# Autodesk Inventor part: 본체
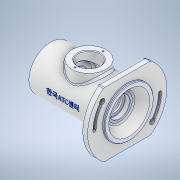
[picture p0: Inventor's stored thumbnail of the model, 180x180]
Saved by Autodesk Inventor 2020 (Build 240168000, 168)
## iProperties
Created: 2022-05
Part Number: 본체
Material: 알루미늄 6061
Document SubType Name: Modeling
Designer: Student
Mass: 685.464 g
Surface Area: 627.299 cm^2
Volume: 253.876 cm^3
Density: 2.7 g/cm^3
Appearance: 알루미늄 - 평지
Author: Student
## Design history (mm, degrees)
sketch "스케치1"
  geometry: L1 (-97.293, 0)-(97.293, 0); L2 (-51, 0)-(-51, 32); L3 (-51, 32)-(51, 32); L4 (51, 32)-(51, 58); L5 (51, 58)-(61, 58); L6 (61, 58)-(61, 36); L7 (61, 36)-(64, 36); L8 (64, 36)-(64, 0); 4 further points
  constraints: 16 end point, 4 perpendicular, 3 coincident, 3 midpoint, 2 horizontal, 2 point on line, 1 parallel, 1 vertical, 1 vertical alignment
  dimensions: "d5" = 64 diameter of L3 L1; "d6" = 116 diameter of L5 L1; "d7" = 72 diameter of L7 L1; "d8" = 102 distance between parallel lines of L4 L2; "d9" = 13 distance between parallel lines of L8 L4; "d10" = 3 distance of L6.end L7.end
revolve "회전1" sketch "스케치1" stored, may be unused: angle "d11" = 90 deg
sketch "스케치2"
  geometry: L1 (-76.744, 0)-(76.744, 0); L2 (-51, 22.5)-(-43, 22.5); L3 (-43, 22.5)-(-43, 24); L4 (-43, 24)-(-40, 24); L5 (-40, 24)-(-40, 22.5); L6 (-40, 22.5)-(-29, 22.5); L7 (-29, 22.5)-(-29, 17.5); L8 (-29, 17.5)-(-26.75, 17.5); L9 (-26.75, 17.5)-(-26.75, 18.5); L10 (-26.75, 18.5)-(-25, 18.5); L11 (-25, 18.5)-(-25, 17.5); L12 (-25, 17.5)-(-14, 17.5); L13 (-14, 17.5)-(-14, 27); L14 (-14, 27)-(24, 27); L15 (24, 27)-(24, 17.5); L16 (24, 17.5)-(35, 17.5); L17 (35, 17.5)-(35, 15); L18 (35, 15)-(40, 15); L19 (40, 15)-(40, 11); L20 (40, 11)-(42.7, 11); L21 (42.7, 11)-(42.7, 15); L22 (42.7, 15)-(49.3, 15); L23 (64, -36)-(64, 36) reference; L24 (64, 30)-(64, 0); L25 (-51, -32)-(-51, 32) reference; L26 (-51, 22.5)-(-51, 0); L27 (50, 15.404)-(50, 20); L28 (50, 20)-(64, 30); L29 (49.3, 15)-(50, 15.404); 5 further points
  constraints: 54 end point, 17 perpendicular, 10 point on line, 2 coincident, 2 horizontal, 2 midpoint, 1 parallel, 1 vertical
  dimensions: "d12" = 45 diameter of L2 L1; "d13" = 48 diameter of L4 L1; "d14" = 54 diameter of L14 L1; "d15" = 30 diameter of L18 L1; "d17" = 60 diameter of L24.start L1; "d18" = 40 diameter of L27.end L1; "d19" = 30 diameter of L22 L1; "d20" = 22 diameter of L20 L1; "d21" = 37 diameter of L10 L1; "d22" = 35 diameter of L12 L1; "d23" = 8 distance of L2.start L2.end; "d24" = 3 distance of L3.end L4.end; "d25" = 11 distance of L11.end L12.end; "d26" = 11 distance of L15.end L16.end; "d27" = 14 distance from line of L23 L27.end; "d28" = 5 distance of L17.end L18.end; "d29" = 29 distance between parallel lines of L23 L17; "d30" = 22 distance between parallel lines of L7 L26; "d32" = 1.75 distance of L9.end L10.end; "d33" = 4 distance between parallel lines of L7 L11; "d35" = 150 deg angle of L22 L29; "d36" = 0.7 horizontal distance of L27.start L22.end; "d37" = 7.3 distance between parallel lines of L27 L21
revolve "회전2" sketch "스케치2" stored, may be unused: angle "d34" = 90 deg
node "작업 평면1"
sketch "스케치3"
  geometry: L1 (51, 32)-(51, -32) reference; C1 r 25 at (-5, 0); 1 further point
  constraints: 1 centre point, 1 horizontal alignment
  dimensions: "d39" = 25 radius of C1; "d40" = 56 distance from line of L1 C1.centre
extrude "돌출1" join sketch "스케치3" stored distance "d41" = 10; taper "d42" = 0 deg
sketch "스케치4"
  geometry: C1 r 25 at (0, 0) reference; 1 further point
hole "구멍1" sketch "스케치4" at (0, 0) diameter "d43" = 32; stored, may be unused: countersink angle "d47" = 90 deg, drill point angle "d49" = 0 deg; dims "d44" = 6, "d45" = 4, "d46" = 2, "d48" = 20
sketch "스케치7"
  geometry: L1 (-33.985, 47)-(33.985, 47); L2 (-33.985, -47)-(33.985, -47); A1 r 58 centre (0, 0) between (-33.985, 47) and (-33.985, -47) reference; A2 r 58 centre (0, 0) between (-33.985, -47) and (33.985, -47); A3 r 58 centre (0, 0) between (33.985, 47) and (-33.985, 47); 1 further point
  constraints: 8 point on circle, 4 end point, 2 centre point, 1 coincident, 1 horizontal, 1 parallel
  dimensions: "d68" = 47 distance from line of point (0, 0) L1; "d69" = 47 distance from line of point (0, 0) L2
extrude "돌출4" cut sketch "스케치7" extent not by distance; stored distance "d70" = 0; taper "d71" = 0 deg
sketch "스케치8"
  geometry: C1 r 25 at (0, 0) reference; 2 further points
  constraints: 1 vertical alignment
  dimensions: "d72" = 20.5 distance of C1.centre point (0, 20.5)
hole "구멍2" sketch "스케치8" at (0, 20.5) diameter "d73" = 2.459; stored, may be unused: countersink angle "d77" = 90 deg, drill point angle "d79" = 118 deg; dims "d74" = 6, "d75" = 4, "d76" = 2, "d78" = 8
node "작업 평면2"
sketch "스케치9"
  geometry: L1 (61, -47)-(61, 47) reference; 2 further points
  constraints: 1 horizontal alignment, 1 other
  dimensions: "d84" = 62 distance from line of L1 point (-1, 0)
feature "엠보싱1" sketch "스케치9" dims "d85" = 0.5, "d86" = 0
fillet "모깎기1" dims "d87" = 0.5
fillet "모깎기2" dims "d88" = 0.6
feature "스레드1" dims "d89" = 18, "d90" = 0
fillet "모깎기3" dims "d91" = 3
chamfer "모따기1" distance "d92" = 1; stored, may be unused: second distance "d93" = 2, angle "d94" = 45 deg
sketch "스케치11"
  geometry: L1 (0, 0)-(-47.496, 0); L2 (0, 0)-(42.689, 0); L3 (-36.77, -30.854)-(0, 0); L4 (0, 0)-(36.77, 30.854); A1 r 48 centre (0, 0) between (-48, 0) and (-36.77, -30.854); A2 r 50.25 centre (0, 0) between (-50.25, 0) and (-38.494, -32.3); A3 r 45.75 centre (0, 0) between (-45.75, 0) and (-35.047, -29.408); A4 r 2.25 centre (-48, 0) between (-45.75, 0) and (-50.25, 0); A5 r 2.25 centre (-36.77, -30.854) between (-38.494, -32.3) and (-35.047, -29.408); A6 r 48 centre (0, 0) between (48, 0) and (36.77, 30.854); A7 r 50.25 centre (0, 0) between (50.25, 0) and (38.494, 32.3); A8 r 45.75 centre (0, 0) between (45.75, 0) and (35.047, 29.408); A9 r 2.25 centre (48, 0) between (45.75, 0) and (50.25, 0); A10 r 2.25 centre (36.77, 30.854) between (38.494, 32.3) and (35.047, 29.408); A11 r 52 centre (0, 0) between (52, 0) and (39.834, 33.425); A12 r 4 centre (48, 0) between (44, 0) and (52, 0); A13 r 44 centre (0, 0) between (44, 0) and (33.706, 28.283); A14 r 4 centre (36.77, 30.854) between (39.834, 33.425) and (33.706, 28.283); A15 r 44 centre (0, 0) between (-44, 0) and (-33.706, -28.283); A16 r 4 centre (-48, 0) between (-44, 0) and (-52, 0); A17 r 52 centre (0, 0) between (-52, 0) and (-39.834, -33.425); A18 r 4 centre (-36.77, -30.854) between (-39.834, -33.425) and (-33.706, -28.283)
  constraints: 37 point on circle, 18 centre point, 8 end point, 8 tangent, 4 point on line, 1 coincident, 1 horizontal, 1 horizontal alignment, 6 other
  dimensions: "d104" = 4.5 radial gap between concentric circles of A3 A2; "d105" = 48 radius of A1; "d106" = 48 radius of A6; "d107" = 4.5 radial gap between concentric circles of A8 A7; "d108" = 40 deg angle of L2 L4; "d109" = 40 deg angle of L1 L3; "d110" = 8 radial gap between concentric circles of A17 A15; "d111" = 8 radial gap between concentric circles of A11 A13
extrude "돌출7" cut sketch "스케치11" extent not by distance; stored distance "d112" = 4.4; taper "d113" = 0 deg
extrude "돌출8" cut sketch "스케치11" distance "d114" = 4.4; taper "d115" = 0 deg
sketch "스케치12"
  geometry: C1 r 4 at (-36.77, -30.854); C2 r 4 at (36.77, 30.854); A1 r 4 centre (-36.77, -30.854) between (-39.834, -33.425) and (-33.706, -28.283) reference; A2 r 4 centre (36.77, 30.854) between (39.834, 33.425) and (33.706, 28.283) reference; 5 further points
  constraints: 2 centre point, 2 coincident
  dimensions: "d116" = 4 radius of C1; "d117" = 4 radius of C2
extrude "돌출9" cut sketch "스케치12" extent not by distance; stored distance "d118" = 0; taper "d119" = 0 deg
fillet "모깎기4" dims "d120" = 3
fillet "모깎기5" dims "d121" = 3
fillet "모깎기6" dims "d122" = 3
node "솔리드1"
pattern_circular "원형 패턴1" dims angle "d81" = 360 deg
feature "A9D066F2-1C7D-4E18-AEED-F7BC21143FA4" dims "d89" = 18, "d90" = 0
other parameters: "d38" = 38, "d83" = 67.75
